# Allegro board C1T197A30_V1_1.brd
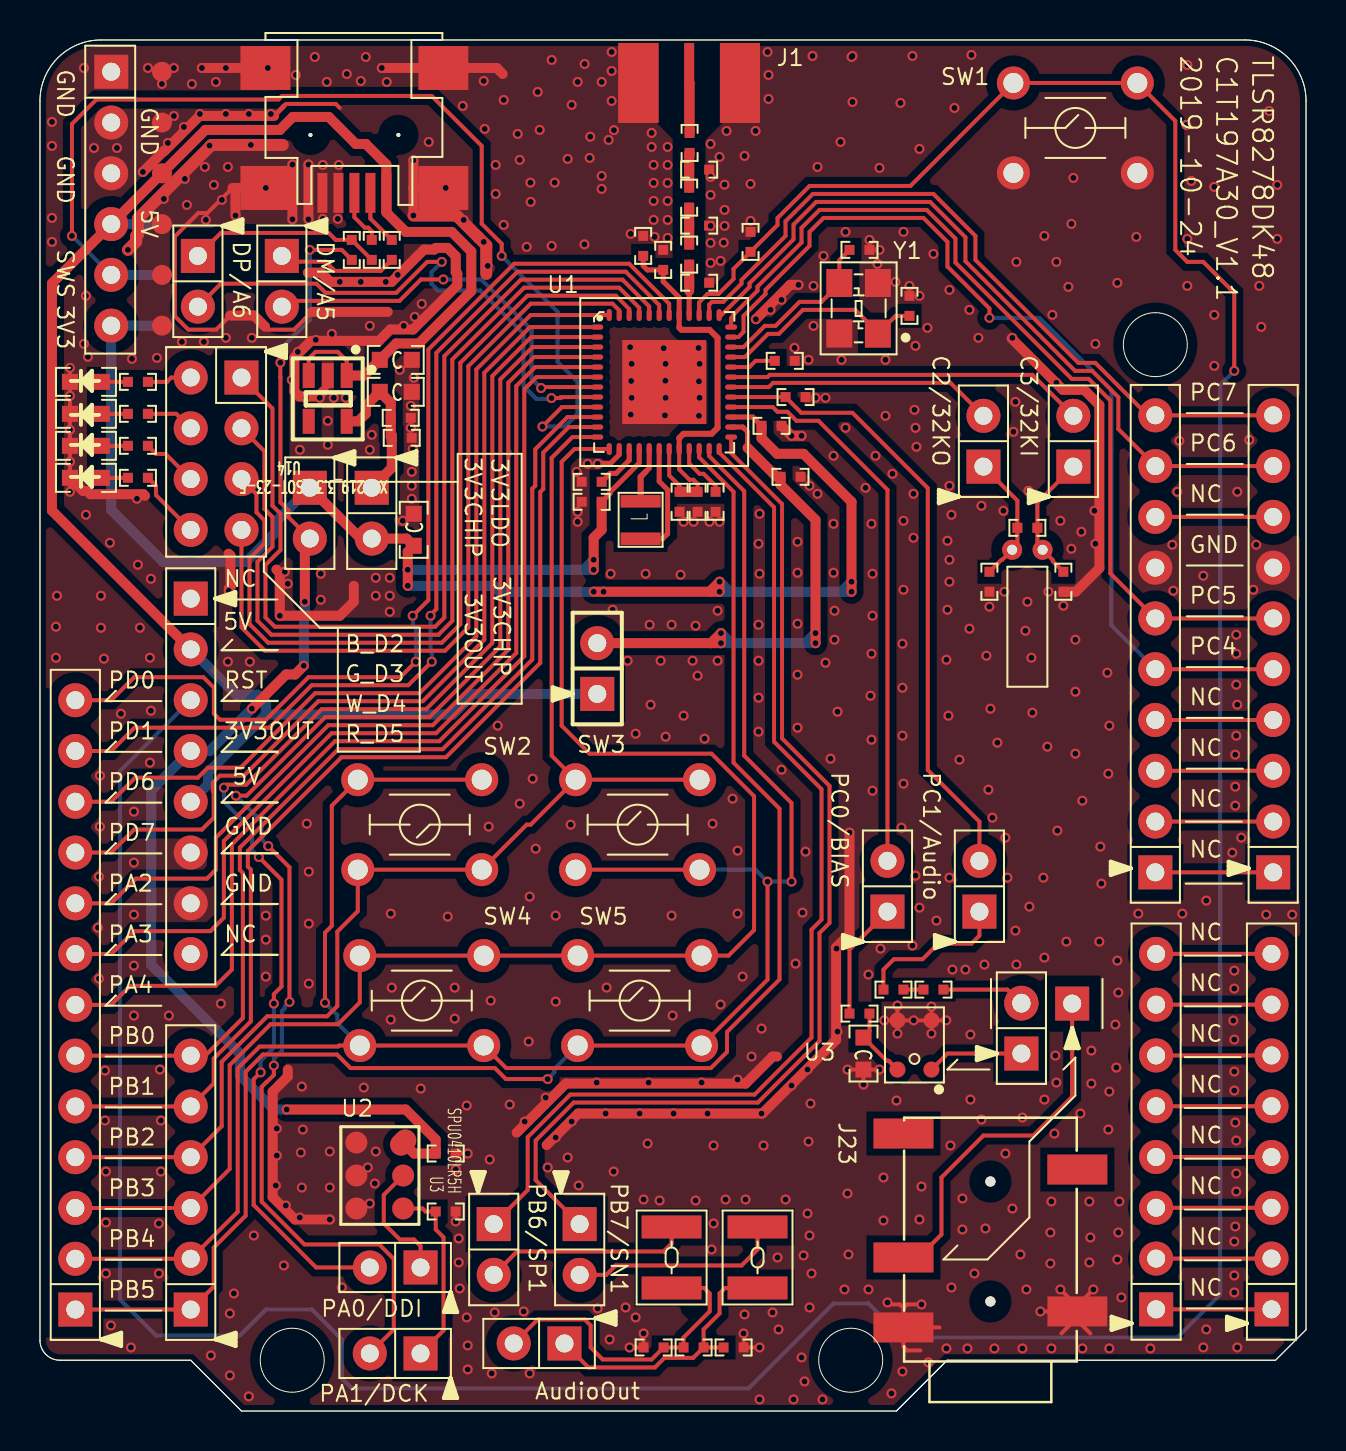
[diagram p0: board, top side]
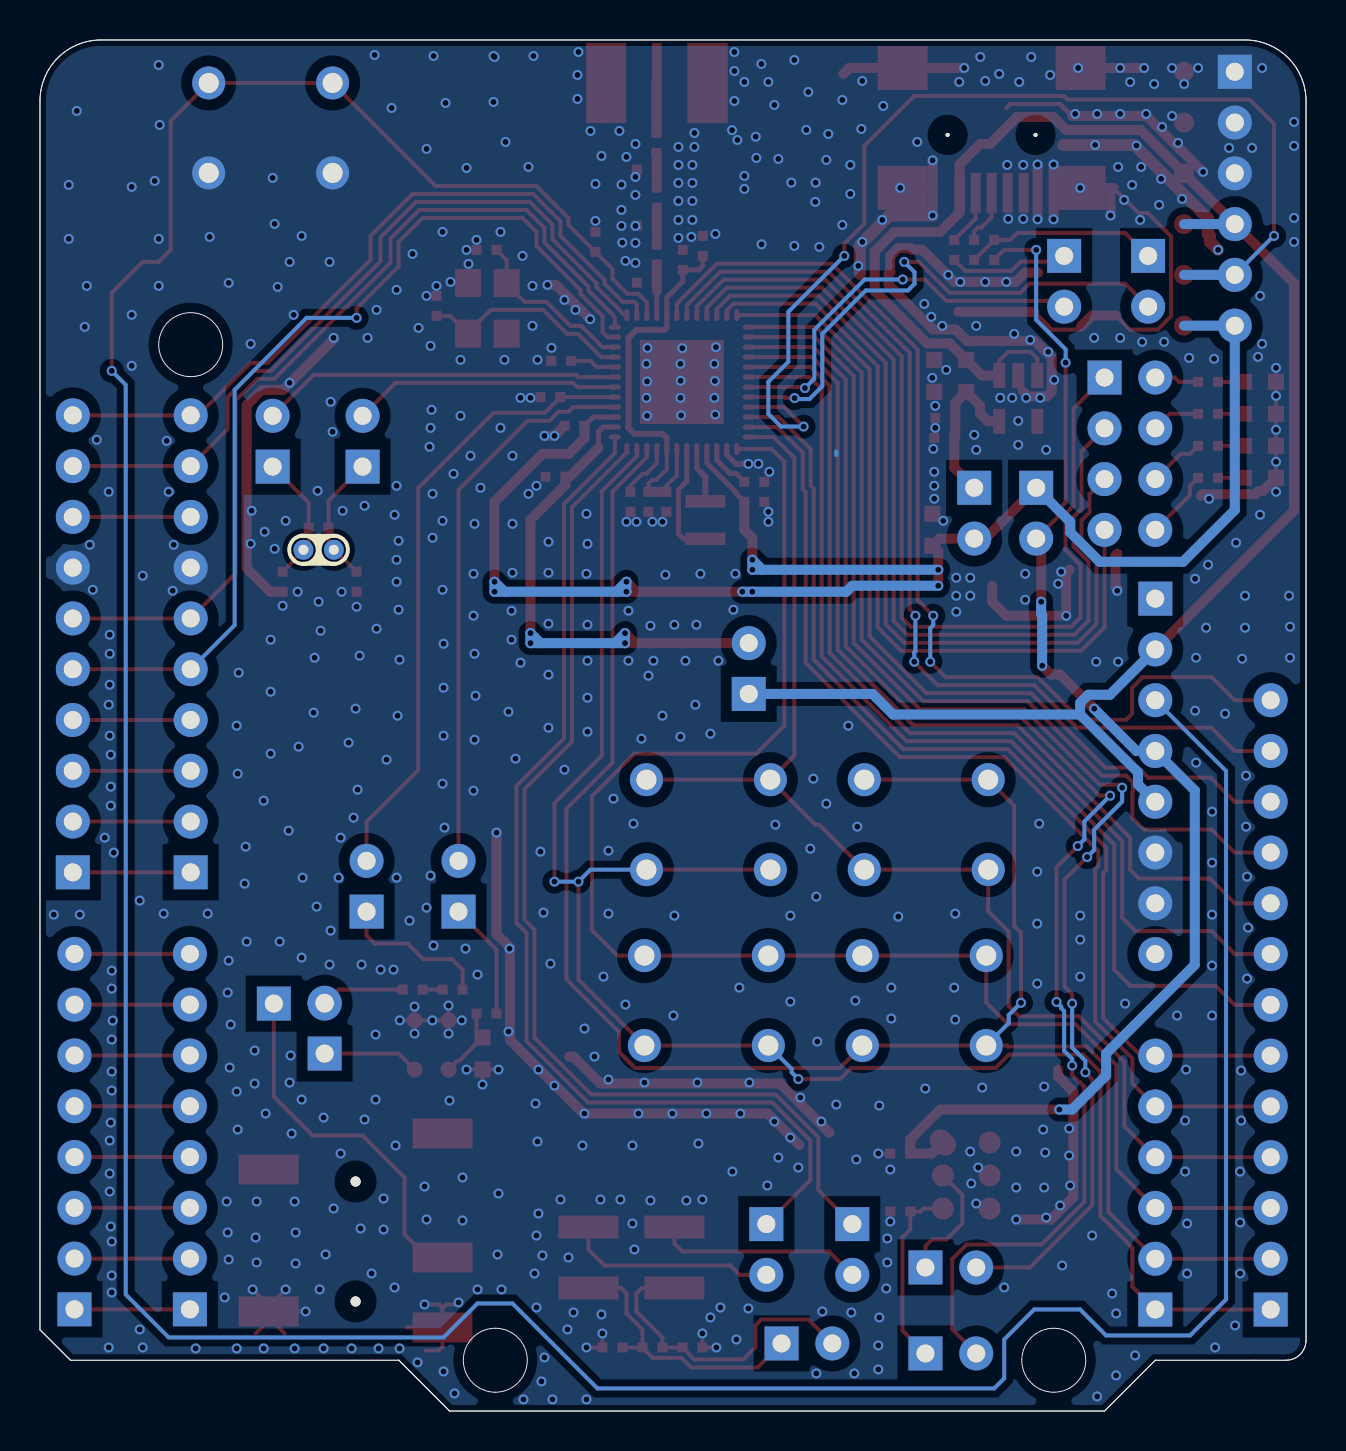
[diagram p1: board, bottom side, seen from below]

Outline 63.34 x 68.58 mm; copper layers: TOP, BOTTOM. Coordinates in mm from the lower left corner of the outline.
Outline path: 0,65.53 arc(0.89,67.69) 3.05,68.58 ; 0,65.53 0,3.54 ; 0,65.53 arc(0.89,67.69) 3.05,68.58 ; 0,65.53 0,3.54 ; 3.05,68.58 60.29,68.58 ; 3.05,68.58 60.29,68.58 ; 0,3.54 arc(0.29,2.83) 1,2.54 ; 0,3.54 arc(0.29,2.83) 1,2.54 ; 1,2.54 7.54,2.54 ; 1,2.54 7.54,2.54 ; 7.54,2.54 10.08,0 ; 7.54,2.54 10.08,0 ; 60.29,68.58 arc(62.45,67.69) 63.34,65.53 ; 60.29,68.58 arc(62.45,67.69) 63.34,65.53 ; 10.08,0 42.85,0 ; 10.08,0 42.85,0 ; 42.85,0 45.39,2.54 ; 42.85,0 45.39,2.54 ; 42.85,0 45.39,2.54 ; 45.39,2.54 61.82,2.54 ; 45.39,2.54 61.82,2.54 ; 63.34,65.53 63.34,4.06 ; 63.34,65.53 63.34,4.06 ; 61.82,2.54 63.34,4.06 ; 61.82,2.54 63.34,4.06 ; 12.62,4.14 arc(14.22,2.54) 12.62,0.94 arc(11.02,2.54) 12.62,4.14 ; 40.56,4.14 arc(42.16,2.54) 40.56,0.94 arc(38.96,2.54) 40.56,4.14 ; 55.8,54.94 arc(57.4,53.34) 55.8,51.74 arc(54.2,53.34) 55.8,54.94

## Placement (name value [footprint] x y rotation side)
C1  0.1uF  [0402]  31.18 57.58 270 top
C2  2.2uF  [0402]  30.18 58.28 270 top
C3  NC  [0402]  41 58.08 180 top
C4  NC  [0402]  43.5 55.28 270 top
C6  1.5pF  [0402]  32.98 59.29 180 top
C7  2pF  [0402]  32.98 62.09 180 top
C8  220pF  [0402]  32.48 57.84 90 top
C9  NC  [0402]  32.98 56.44 180 top
C10  NC  [0402]  47.5 41.48 90 top
C11  NC  [0402]  51.2 41.48 90 top
C13  1uF  [0402]  36.6 49.28 0 top
C14  1uF  [0402]  27.6 46.48 0 top
C15  1uF  [0402]  35.55 58.48 270 top
C16  1uF  [0402]  27.6 45.48 180 top
C17  0.1uF  [0402]  32.9 45.48 270 top
C18  1uF  [0402]  32 45.48 270 top
C19  1uF  [0402]  33.8 45.48 270 top
C20  NC  [0402]  30.7 3.18 0 top
C21  220nF  [0402]  32.7 3.18 0 top
C22  0.1uF  [0402]  20.3 12.88 0 top
C23  NC  [0402]  34.7 3.18 0 top
C24  10nF  [0402]  44.7 21.08 0 top
C25  10pF  [0402]  37.8 50.72 180 top
C26  4.7uF  [0603C]  41.2 17.88 270 top
C27  1uF  [0402]  37.55 46.73 0 top
C29  10uF  [0603C]  18.7 44.08 90 top
C30  10uF  [0603C]  17.8 52.58 0 top
C31  10uF  [0603C]  17.8 50.98 0 top
C32  1nF  [0402]  18.1 48.68 0 top
C33  0.1uF  [0402]  18.05 49.68 0 top
C34  1uF  [0402]  37.26 52.53 0 top
D1  Blue  [0603-LED]  2.3 51.48 180 top
D2  Green  [0603-LED]  2.3 49.88 180 top
D3  White  [0603-LED]  2.3 48.28 180 top
D4  Red  [0603-LED]  2.3 46.68 180 top
J1  RFIN  [SMA-H]  32.48 66.43 270 top
J2  32KPC3  [HDR254F-1X2X850]  51.7 49.78 270 top
J4  32KPC2  [HDR254F-1X2X850]  47.2 49.78 270 top
J6  HEADER 13  [HDR254F-1X13X850]  1.77 35.56 270 top
J7  Left_Ardunio  [HDR254F-1X8X850]  7.54 22.86 90 top
J8  Right_Ardunio  [HDR254F-1X10X850]  55.8 49.81 270 top
J9  Right_Telink  [HDR254F-1X10X850]  61.7 49.81 270 top
J11  Right_Ardunio  [HDR254F-1X8X850]  55.84 22.87 270 top
J12  Right_Telink  [HDR254F-1X8X850]  61.61 22.87 270 top
J13  Left_Ardunio  [HDR254F-1X6X850]  7.54 17.78 270 top
J16  SDMB4  [HDR254F-1X2X850]  22.7 6.81 90 top
J17  SDMB5  [HDR254F-1X2X850]  27 6.81 90 top
J18  Debug  [HDR254F-1X6X850_TELINKDEBUG]  3.56 54.29 90 top
J20  MICPC0  [HDR254F-1X2X850]  42.4 27.52 270 top
J22  MICPC1  [HDR254F-1X2X850]  47 27.52 270 top
J23  PJ327  [PJ-327]  47.55 2.48 180 top
J26  USB_MiniABF  [USB-MINI-F5]  15.73 60.93 180 top
J27  DM/A5  [HDR254F-1X2X850]  12.1 55.24 90 top
J28  DP/A6  [HDR254F-1X2X850]  7.9 55.24 90 top
J29  Chip3V3  [HDR254F-1X2X850]  16.6 43.64 90 top
J35  IO3V3  [HDR254F-1X2X850]  13.5 43.64 90 top
J36  MICIN  [HDR254F-1X2X850]  49.1 20.42 270 top
J37  LINEIN  [HDR254F-1X2X850]  49.1 20.38 0 top
J38  LED  [HDR254F-2X4X850]  10.08 41.54 90 top
J39  AudioOut  [HDR254F-1X2X850]  23.7 3.38 0 top
J40  DMICCK  [HDR254F-1X2X850]  16.5 2.88 0 top
J41  DMICDI  [HDR254F-1X2X850]  16.5 7.18 0 top
J42  RF_SOC_5V  [HDR254F-1X2X850]  27.88 38.41 270 top
L2  2.4nH  [0402]  32.48 60.69 90 top
L3  4.7uH  [2X2_5MM]  36.8 33.28 90 top
L4  150uH  [INDM3025X25]  31.6 7.68 270 top
L5  150uH  [INDM3025X25]  35.9 7.68 270 top
L6  1.5nH  [0402]  32.5 63.43 90 top
R1  NC  [0402]  49.4 44.18 0 top
R2  100K  [0402]  20.3 9.98 180 top
R3  1K  [0402]  4.9 51.48 180 top
R4  1K  [0402]  4.9 49.88 180 top
R5  1K  [0402]  4.9 48.28 180 top
R6  1K  [0402]  4.9 46.68 180 top
R7  0R  [0402]  41 19.88 0 top
R8  000R  [0402]  42.7 21.08 0 top
R10  33  [0402R]  17.6 58.08 270 top
R11  33  [0402R]  16.6 58.08 270 top
R12  NC/1.5K  [0402R]  15.6 58.08 270 top
SW1  SW4PIN_4.5x4.5  [BUTDIP4P_5P0X3P0]  51.8 64.18 0 top
SW2  Key1  [BUTDIP4P_5P0X3P0]  19 29.33 180 top
SW3  Key2  [BUTDIP4P_5P0X3P0]  29.9 29.33 0 top
SW4  Key3  [BUTDIP4P_5P0X3P0]  19.1 20.53 0 top
SW5  Key4  [BUTDIP4P_5P0X3P0]  30 20.53 0 top
U1  TLSR8278F1KET48  [QFN_7X7_48PIN_0P5_4P20X4P20]  31.23 51.47 0 top
U2  SPM0423HM4H-WB  [DMIC_SPM0423HM4H-WB]  17 11.78 270 top
U3  MWW7037AT2  [GA_BFA423_A83]  43.75 18.31 180 top
U4  CE1132-33M  [SOT-23-5]  14.4 50.65 180 top
Y1  24MHz-12pF-+/-20ppm  [OSCCC250X320X110]  40.96 55.16 180 top
Y2  32.768KHz - 9pf - +/-20ppm  [OSC_2X6]  49.4 39.08 90 top

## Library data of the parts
C1 C2 C13 C16-C19 C22 C27 C29-C34 = C1005X5R1C104K
C3 C4 C20 C23 = C1005_NC
C6-C11 = C1608_NC
C14 C15 C24 = C1005X5R1C105K
C21 = C1005X5R1C224M
C25 = C1005C0G1H223J
C26 = C1608X5R0J475M
D1-D4 = 0603D_Green
J1 = SMA_JACK_2
J2 J4 J16 J17 J20 J22 J27-J29 J35-J37 J39-J42 = B2S_3: User Part Number: pn; Tolerance: RichardLC
J6 = HEADER 13: User Part Number: pn; Tolerance: RichardLC
J7 J11 J12 = HEADER 8: User Part Number: pn; Tolerance: RichardLC
J8 J9 = HEADER 10: Tolerance: RichardLC; User Part Number: pn
J13 = HEADER 6: User Part Number: pn; Tolerance: RichardLC
J18 = CON_0.54mm_2x6: User Part Number: pn; Tolerance: RichardLC
J23 = PJ327_2
J26 = USB_MiniABF_5pin: Tolerance: RichardLC; User Part Number: pn
J38 = HEADER 4X2: User Part Number: pn; Tolerance: RichardLC
L2 L6 = MLK1608_000R
L3 = IND_0
L4 L5 = IND_150uH_3025
R1 = RS0603K102JT
R2 = RS0402K104JT
R3-R6 = RS0402K102JT
R7 R8 = RS0402K472JT
R10 R11 = RS0603K330JT
R12 = RS0603K152JT
SW1-SW5 = SW4PIN_0.5
U1 = TLSR8278F1KET48_2
U2 = LD1117/SO_0
U3 = MULPS4CX-RM5_0
U4 = XC6219_6.3V_SOT-23-5
Y1 = CRYSTAL4/SM_0: Tolerance: RichardLC
Y2 = OSC_2x6_2pin_16Mhz

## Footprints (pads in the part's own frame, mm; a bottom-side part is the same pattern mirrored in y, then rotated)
2X2_5MM
  rect 0.625x2 smd: 1(10.35,6.75) 2(12.225,6.75)
0402
  rect 0.5x0.5 smd: 1(-0.5,0) 2(0.5,0)
0402R
  rect 0.5x0.5 smd: 1(-0.5,0) 2(0.5,0)
0603-LED
  rect 0.8x0.8 smd: A(-0.8,0) C(0.8,0)
0603C
  rect 0.8x0.8 smd: 1(-0.8,0) 2(0.8,0)
BUTDIP4P_5P0X3P0
  round 1.65 hole 1: 1(-3.1,2.25) 2(-3.1,-2.25) 3(3.1,2.25) 4(3.1,-2.25)
DMIC_SPM0423HM4H-WB
  round 1.1 smd: 1(-1.65,-1.17) 2(0,-1.17) 3(1.65,-1.17) 4(1.65,1.17) 5(0,1.17)
  oval 1.4x1.1 smd rot 135: 6(-1.65,1.17)
GA_BFA423_A83
  round 0.8 smd: 1(-0.85,1.23) 2(-0.85,-1.23) 3(0.85,-1.23) 4(0.85,1.23)
HDR254F-1X2X850
  rect 1.7x1.7 hole 0.9: 1(2.54,0)
  round 1.7 hole 0.9: 2(0,0)
HDR254F-1X6X850
  rect 1.7x1.7 hole 0.9: 1(12.7,0)
  round 1.7 hole 0.9: 2(10.16,0) 3(7.62,0) 4(5.08,0) 5(2.54,0) 6(0,0)
HDR254F-1X6X850_TELINKDEBUG
  rect 1.7x1.7 hole 0.9: 1(12.7,0)
  round 1.7 hole 0.9: 2(10.16,0) 3(7.62,0) 4(5.08,0) 5(2.54,0) 6(0,0)
  round 1 smd: 7(0,-2.54) 8(2.54,-2.54) 9(5.08,-2.54) 10(7.62,-2.54) 11(10.16,-2.54) 12(12.7,-2.54)
HDR254F-1X8X850
  rect 1.7x1.7 hole 0.9: 1(17.78,0)
  round 1.7 hole 0.9: 2(15.24,0) 3(12.7,0) 4(10.16,0) 5(7.62,0) 6(5.08,0) 7(2.54,0) 8(0,0)
HDR254F-1X10X850
  rect 1.7x1.7 hole 0.9: 1(22.86,0)
  round 1.7 hole 0.9: 2(20.32,0) 3(17.78,0) 4(15.24,0) 5(12.7,0) 6(10.16,0) 7(7.62,0) 8(5.08,0) 9(2.54,0) 10(0,0)
HDR254F-1X13X850
  rect 1.7x1.7 hole 0.9: 1(30.48,0)
  round 1.7 hole 0.9: 2(27.94,0) 3(25.4,0) 4(22.86,0) 5(20.32,0) 6(17.78,0) 7(15.24,0) 8(12.7,0) 9(10.16,0) 10(7.62,0) 11(5.08,0) 12(2.54,0) 13(0,0)
HDR254F-2X4X850
  rect 1.7x1.7 hole 0.9: 1(10.16,0)
  round 1.7 hole 0.9: 2(10.16,2.54) 3(7.62,0) 4(7.62,2.54) 5(5.08,0) 6(5.08,2.54) 7(2.54,0) 8(2.54,2.54)
INDM3025X25
  rect 1.15x3 smd: 1(-1.525,0) 2(1.525,0)
OSC_2X6
  round 1 hole 0.5: 1(4,0.76) 2(4,-0.76)
OSCCC250X320X110
  rect 1.3x1.4 smd: 1(-0.965,1.265) 2(-0.965,-1.265) 3(0.965,-1.265) 4(0.965,1.265)
PJ-327
  round 0.5 hole 1: (0,-3) (0,-9)
  rect 3x1.5 smd: 1(-4.35,-2.5) 2(4.35,-5.2) 3(-4.35,-9.6) 4(4.35,-11.4) 5(4.35,-1.7)
QFN_7X7_48PIN_0P5_4P20X4P20
  oval 0.6x0.26 smd: 1(-3.35,2.75) 2(-3.35,2.25) 3(-3.35,1.75) 4(-3.35,1.25) 5(-3.35,0.75) 6(-3.35,0.25) 7(-3.35,-0.25) 8(-3.35,-0.75) 9(-3.35,-1.25) 10(-3.35,-1.75) 11(-3.35,-2.25) 12(-3.35,-2.75) 25(3.35,-2.75) 26(3.35,-2.25) 27(3.35,-1.75) 28(3.35,-1.25) 29(3.35,-0.75) 30(3.35,-0.25) 31(3.35,0.25) 32(3.35,0.75) 33(3.35,1.25) 34(3.35,1.75) 35(3.35,2.25) 36(3.35,2.75)
  oval 0.26x0.6 smd: 13(-2.75,-3.35) 14(-2.25,-3.35) 15(-1.75,-3.35) 16(-1.25,-3.35) 17(-0.75,-3.35) 18(-0.25,-3.35) 19(0.25,-3.35) 20(0.75,-3.35) 21(1.25,-3.35) 22(1.75,-3.35) 23(2.25,-3.35) 24(2.75,-3.35) 37(2.75,3.35) 38(2.25,3.35) 39(1.75,3.35) 40(1.25,3.35) 41(0.75,3.35) 42(0.25,3.35) 43(-0.25,3.35) 44(-0.75,3.35) 45(-1.25,3.35) 46(-1.75,3.35) 47(-2.25,3.35) 48(-2.75,3.35)
  rect 4.2x4.2 smd: 49(0,0)
SMA-H
  rect 4x0.5 smd: 1(0,0)
  rect 4x2 smd: 2(0,-2.54) 3(0,2.54) 4(0,-2.54) 5(0,2.54)
SOT-23-5
  rect 0.6x1.25 smd: 1(-0.95,-1.145) 2(0,-1.145) 3(0.95,-1.145) 4(0.95,1.145) 5(-0.95,1.145)
USB-MINI-F5
  round 0.2 hole 0.9 unplated: (-2.2,-2.9) (2.2,-2.9)
  rect 0.5x2 smd: 1(-1.6,0) 2(-0.8,0) 3(0,0) 4(0.8,0) 5(1.6,0)
  rect 2.5x2.2 smd: 6(-4.45,-6.25) 7(4.45,-6.25) 8(-4.45,-0.25) 9(4.45,-0.25)

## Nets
1V4: C1.2 C2.2 C17.1 C18.1 U1.19(VDD1V2) U1.20(AVDD1V2#20) U1.41(AVDD1V2#41)
3V3: C31.1 C32.1 C33.1 J29.1 U4.5(VOUT)
GND: C1.1 C2.1 C3.1 C4.1 C6.1 C7.1 C9.1 C10.1 C11.1 C13.2 C14.1 C15.1 C16.2 C17.2 C18.2 C19.2 C20.1 C22.2 C23.2 C25.1 C26.2 C27.2 C29.2 C30.2 C31.2 C32.2 C33.2 C34.2 D1.C(CATHODE) D2.C(CATHODE) D3.C(CATHODE) D4.C(CATHODE) J1.2 J1.3 J1.4 J1.5 J7.6 J7.7 J8.7 J9.7 J18.1 J18.2 J18.3 J18.10 J18.11 J18.12 J23.1 J23.5 J26.4(ID) J26.5(GND) J26.6(S1) J26.7(S2) J26.8(S3) J26.9(S4) R2.1 SW1.2 SW1.4 U1.14(DVSS) U1.49(GND) U2.1(GND#1) U2.2(SE) U2.3(GND#3) U3.2(GND#2) U3.3(GND#3) U4.2(VSS) Y1.2 Y1.4
TL_32KI_C3: J2.2 U1.31(P1/URX/SCK/32KIN/C[3])
TL_32KO_C2: J4.2 U1.30(P0/7816TRX/UTX/SDA/32KO/C[2])
TL_ANT: C8.1 C9.2 U1.40(ANT)
TL_AS0_C5: J8.6 J9.6 U1.36(P3N/URX/ATSEL0/C[5])
TL_AS1_C6: J8.9 J9.9 U1.37(CYC2LNA/ATSEL1/P4N/C[6])
TL_AS2_C7: J8.10 J9.10 U1.38(CYC2PA/ATSEL2/P5N/C[7])
TL_AUDIO_C1: C25.2 J22.2 U1.29(SCK/P1N/P0/AUDIO_IN/C[1])
TL_C0: J20.2 U1.28(SDA/P4N/URTS/MDEC/C[0])
TL_CK_A4: J6.7 U1.6(CK/SCL/URTS/P2/A[4])
TL_CN_D6: J6.11 U1.48(CN/URX/ATSEL0/D[6])
TL_D0: J6.13 U1.42(CYC2LNA/CMP_D/7816TRX/UTX/MDEC/)
TL_D1: J6.12 U1.43(CYC2PA/CMP_DF/UCTS/D[1])
TL_D7: J6.10 U1.1(CK/SCL/I2SBCK/7816TRX/UTX/D[7])
TL_DI_A3: J6.8 U1.5(DI/SDA/UCTS/P1/A[3])
TL_DM_A5: J27.2 U1.7(DM/A[5])
TL_DMICCK_A1: J40.2 U1.3(DMIC_CLK/7816CLK/I2SCLK/A[1])
TL_DMICDI_A0: J41.2 U1.2(DMIC_DI/P0N/URX/MDEC/A[0])
TL_DO_A2: J6.9 U1.4(DO/UTX/P0/A[2])
TL_DP_A6: J28.2 U1.8(DP(SWS)/A[6])
TL_IO: C22.1 J7.4 J35.2 R12.2 U2.6(POWER)
TL_KEY_B2: J6.4 J13.4 SW2.1 SW2.3 SW3.1 SW3.3 U1.12(P5/UCTS/CYC2LNA/B[2])
TL_KEY_B3: J6.3 J13.3 SW4.1 SW4.3 SW5.1 SW5.3 U1.13(P0N/URTS/CYC2PA/B[3])
TL_KEY_B4: J6.2 J13.2 SW2.2 SW2.4 SW4.2 SW4.4 U1.22(SDMP0/P4/CMP_D/B[4])
TL_KEY_B5: J6.1 J13.1 SW3.2 SW3.4 SW5.2 SW5.4 U1.23(SDMN0/P5/CMP_DF/B[5])
TL_P0_D5: J38.7 U1.47(P0/CMP_D/P0N/D[5])
TL_P1N_D3: J38.3 U1.45(P1N/I2SSDI/7816TRX/UTX/D[3])
TL_P2_C4: J8.5 J9.5 U1.35(P2/UCTS/P0/C[4])
TL_P2N_D4: J38.5 U1.46(SWM/I2SSDO/P2N/D[4])
TL_P3_D2: J38.1 U1.44(CN/I2SLR/P3/D[2])
TL_RST: C15.2 J7.3 SW1.1 SW1.3 U1.39(RESETB)
TL_SDMN1_B7: J17.1 U1.25(SDMN1/DO/URX/B[7])
TL_SDMP1_B6: J16.1 U1.24(SDMP1/DI/SDA/URTS/B[6])
TL_SWS_A7: J18.5 J18.8 U1.9(SWS/URTS/A[7])
TL_URX_B0: J6.6 J13.6 U1.10(P3/URX/ATSEL1/MDEC/B[0])
TL_UTX_B1: J6.5 J13.5 U1.11(P4/UTX/ATSEL2/B[1])
TL_VBUS: C27.1 J42.2 U1.26(VBUS)
TL_VDD: C13.1 C16.1 C29.1 J18.6 J18.7 J29.2 J35.1 U1.16(VDD_IO) U1.27(VDD3)
TL_XC1: C3.2 U1.34(XC1) Y1.3
TL_XC2: C4.2 U1.33(XC2) Y1.1
USB_5V: C30.1 J7.2 J7.5 J18.4 J18.9 J26.1(V_BUS) J42.1 U4.1(VIN) U4.3(CE)
N19472288: J38.4 R4.1
N19472291: J38.8 R6.1
N19472372: J16.2 L4.1
N19472375: J17.2 L5.1
N19472414: C20.2 C21.1 J39.2 L4.2
N19472431: C21.2 C23.1 J39.1 L5.2
N19472505: J38.2 R3.1
N19497696: J38.6 R5.1
N19519268: C11.2 J2.1 R1.2 Y2.2
N19519271: C10.2 J4.1 R1.1 Y2.1
N19526123: J28.1 R11.2 R12.1
N19526133: J26.3(D+) R11.1
N19526168: J26.2(D-) R10.1
N19527038: J27.1 R10.2
N19581488: J20.1 R7.1
N19581502: C26.1 R7.2 U3.4(VDD)
N19581635: C24.1 R8.2
N19581732: J23.2 J37.1
N19602515: C24.2 J36.2 J37.2
N19603583: J22.1 R8.1
N19606656: J40.1 R2.2 U2.4(CLOCK)
N19606659: J41.1 U2.5(DATA)
N19611817: J8.4 J9.4
N19611824: J8.3 J9.3
N19611831: J8.2 J9.2
N19611838: J8.1 J9.1
N19611845: J8.8 J9.8
N19611852: J11.8 J12.8
N19611859: J11.6 J12.6
N19611866: J11.7 J12.7
N19611873: J11.5 J12.5
N19611880: J11.4 J12.4
N19611887: J11.3 J12.3
N19611894: J11.2 J12.2
N19611901: J11.1 J12.1
N19648539: C34.1 U1.32(VMID)
N19648573: C14.2 U1.15(VDD1V)
N19648583: L3.1 U1.18(VDCDC)
N19648603: L3.2 U1.17(VDCDC_SW)
N19648651: C19.1 U1.21(VDD_F)
N19650305: C6.2 C8.2 L2.1
N19650315: C7.2 L2.2 L6.1
N19656188: J1.1 L6.2
N194723011: D4.A(ANODE) R6.2
N194723090: D1.A(ANODE) R3.2
N194723171: D2.A(ANODE) R4.2
N194723250: D3.A(ANODE) R5.2
N195815302: J36.1 U3.1(OUTPUT)

Pads without a net: J7 1 8; J23 3 4; U4 4

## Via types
v1: diameter 0.5, hole 0.3, TOP to BOTTOM, 735 vias

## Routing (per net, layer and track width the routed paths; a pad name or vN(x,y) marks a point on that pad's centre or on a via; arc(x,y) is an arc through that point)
1V4: length 20
  TOP w0.2: C17.1 32.9,46.38 32.7,46.58 32.5,46.58 31.98,47.1 U1.20 ; C18.1 32,46.28 31.48,46.8 U1.19
  TOP w0.25: U1.20 31.98,48.66 ; 31.98,54.2 U1.41 31.98,55.7 31.18,56.5 C1.2 30.38,57.08 30.18,57.28 C2.2
  TOP w0.3: 31.98,54.2 32.1,54.08 33.5,54.08 33.9,53.68 33.9,49.18 33.6,48.88 32.19,48.88 31.98,48.66
  TOP w0.5: C18.1 C17.1
3V3: length 8
  TOP w0.5: U4.5 15.93,49.51 16.3,49.88 16.3,50.28 C31.1 17.55,50.43 C33.1 17.55,48.73 C32.1 17.6,47.18 J29.1
GND: length 212.7
  TOP w0.2: J23.5 45,4.18 ; J23.5 43.2,3.21 43.38,3.03 44.05,3.03 ; J23.5 43.2,5.15 ; C26.2 v1(40.4,17.08) ; C26.2 v1(41.2,16.33) ; C26.2 v1(42,17.08) ; 52.55,3.88 51.9,4.53 51.9,4.68 ; J23.1 51.9,4.68 ; J23.1 51.9,5.23 ; J23.1 v1(50.05,4.98) ; 51.9,4.68 51.1,3.88 ; U4.2 14.4,51.23 14.17,51 ; 9.63,61.18 8.38,59.92 7.92,59.92 6.75,58.75 6.75,54.76 7.42,54.09 8.81,54.09 9.52,54.8 ; v1(1.5,52.18) D1.C v1(1.5,50.78) D2.C v1(1.5,49.08) D3.C v1(1.5,47.48) D4.C v1(1.5,45.98) ; U3.2 v1(45.34,19.54) ; U3.2 v1(44.6,18.88) ; U3.2 v1(44.6,20.23) ; U3.2 v1(43.71,19.54) U3.3 ; v1(30.2,3.88) C20.1 v1(29.5,3.18) ; 51.9,5.23 51.9,5.28 v1(52.7,6.08) ; 51.9,5.23 v1(51.05,6.08) ; U3.3 v1(42.9,20.28) ; U3.3 v1(42.9,18.88) ; U3.3 v1(42.24,19.54) ; 43.2,5.15 43.02,5.33 42.3,5.33 ; 43.2,5.15 43.38,5.33 v1(44.1,5.33) ; 15,65.18 14.8,65.38 12.31,65.38 12.21,65.27 ; 13.6,54.98 12.71,54.09 11.41,54.09 11.26,54.24 ; v1(36,3.18) C23.2 v1(35.2,3.88) ; R2.1 v1(20.8,9.48) ; C22.2 v1(21.4,12.88)
  TOP w0.25: 12.21,65.27 11.71,64.78 ; U1.14 28.98,47.84 28.52,47.38
  TOP w0.3: v1(27.9,47.38) 28.52,47.38
  TOP w0.5: 11.71,64.78 7.98,64.78 6.24,63.04 6.21,63.04 v1(5.15,61.98) ; v1(12.63,62.35) v1(12.63,59.61) ; 9.52,54.8 10.7,54.8 11.26,54.24 ; v1(11.4,67.18) J26.7 v1(8.1,67.18) ; 18.68,61.18 v1(18.68,59.8) ; 18.68,61.18 v1(18.68,62.56) ; 18.68,61.18 J26.8 v1(20.3,61.18) ; D4.C 2.16,46.02 2.37,46.02 2.53,45.86 5.18,45.86 5.26,45.78 ; 36.87,17.73 36.65,17.73 35.3,16.38 26.31,16.38 23.85,13.92 ; v1(37.95,56.33) 37.53,56.33 v1(35.82,54.61) ; 15.7,41.28 15.7,40.48 15,39.78 v1(12,39.78) 12,41.92 11.83,42.09 ; v1(13.43,62.35) v1(13.43,59.61) ; 13.4,56.94 14.06,56.94 14.52,56.48 v1(15,56.48) v1(16.05,56.48) v1(17.3,56.48) 17.59,56.48 19.21,58.1 19.73,58.1 19.81,58.18 20.39,58.18 20.8,57.77 20.8,56.97 20.88,56.89 20.88,56.31 18.67,54.1 17.53,54.1 16.96,53.53 13.56,53.53 12.73,52.7 12.73,51 12.97,50.75 13.92,50.75 14.17,51 ; v1(40.5,28.93) 40.5,23.86 39.83,23.19 39.83,18.57 36.14,14.88 v1(36.1,14.88) v1(33.4,14.88) v1(31.7,14.88) v1(30,14.88) v1(28.3,14.88) 26.93,14.88 25.35,13.3 ; v1(11.3,61.18) J26.9 9.78,61.18 ; 12.4,17.08 12.4,16.73 11.64,15.97 11.64,10.7 12.76,9.58 v1(14.5,9.58) ; 9.78,61.18 v1(9.78,59.8) ; 9.78,61.18 9.63,61.18 ; 23.15,66.88 22.85,67.18 J26.6 v1(17.1,67.18) ; v1(38.1,48.78) v1(37.6,48.78) C13.2 ; 13.6,54.98 17.4,54.98 ; 48.61,53.65 51.18,51.08 52.24,51.08 53,50.32 53,42.16 51.82,40.98 C11.1 ; v1(9.45,41.03) 9.45,41.13 9.53,41.21 9.53,42.79 9.43,42.88
  TOP w0.6: 12.15,63.33 v1(10.55,63.33) 8.58,63.33 4.91,59.66 4.91,58.87 4.81,58.77 4.81,58.49 v1(4.4,58.08) ; 22.33,56.88 22.33,58.31 21.93,58.71 20.84,59.8 v1(18.68,59.8)
  BOTTOM w0.2: 23.5,48 23.5,47.82
  vias: v1(0.6,64.48) v1(0.6,63.28) v1(0.6,59.68) v1(0.6,58.48) v1(0.85,40.78) v1(0.8,39.23) v1(0.8,37.68) v1(2.2,67.18) v1(2.2,53.38) v1(2.3,55.78) v1(2.3,44.83) v1(2.4,52.73) v1(2.7,63.18) v1(2.9,24.18) v1(3.05,40.78) v1(3.05,39.18) v1(3,31.78) v1(3,29.23) v1(2.95,26.73) v1(2.95,21.63) v1(3.2,37.63) v1(3.25,17.03) v1(3.25,14.53) v1(3.3,11.98) v1(3.3,9.43) v1(3.3,6.88) v1(3.5,43.43) v1(3.55,4.28) v1(3.85,63.18) v1(4.05,34.88) v1(4.55,3.18) v1(4.6,52.63) v1(4.7,29.98) v1(4.7,27.43) v1(4.7,24.83) v1(4.7,22.28) v1(4.7,19.78) v1(4.85,45.63) v1(4.9,42.33) v1(5,39.18) v1(5.4,67.18) v1(5.55,41.63) v1(5.5,37.68) v1(5.55,35.03) v1(5.5,32.43) v1(5.85,52.68) v1(6,17.08) v1(6.05,14.53) v1(6.05,11.98) v1(5.95,9.38) v1(5.95,6.88) v1(6.1,66.38) v1(6.2,60.63) v1(6.4,63.43) v1(6.45,19.78) v1(6.7,67.18) v1(6.7,64.78) v1(7.1,53.48) v1(7.2,64.23) v1(7.25,61.63) v1(7.35,60.33) v1(7.6,66.38) v1(8,64.88) v1(8.25,62.23) v1(8.2,53.48) v1(8.3,59.58) v1(8.48,63.3) v1(8.55,2.78) v1(8.7,61.33) v1(8.8,66.48) v1(9.1,60.58) v1(9.05,20.38) v1(9.3,67.18) v1(9.3,64.88) v1(9.3,53.68) v1(9.4,62.23) v1(9.4,37.48) v1(9.5,4.88) v1(9.5,1.78) v1(9.7,5.88) v1(10.45,64.88) v1(10.45,0.73) v1(10.5,37.48) v1(10.6,53.68) v1(10.7,8.78) v1(11.3,24.78) v1(11.3,23.58) v1(11.3,21.73) v1(11.55,64.88) v1(11.85,14.13) v1(11.85,12.78) v1(11.8,11.28) v1(12.25,41.98) v1(12.2,7.28) v1(12.3,10.28) v1(12.4,41.38) v1(12.6,51.58) v1(12.8,66.83) v1(12.9,52.98) v1(13,48.08) v1(13,9.68) v1(13.1,16.23) v1(13.05,12.93) v1(13.1,11.18) v1(13.15,14.08) v1(13.3,50.68) v1(13.35,29.38) v1(13.45,26.98) v1(13.45,24.38) v1(13.45,21.38) v1(13.75,67.73) v1(13.8,53.58) v1(14,50.68) v1(14.05,41.88) v1(14.05,40.58) v1(14.15,62.33) v1(14.15,59.63) v1(14.35,66.48) v1(14.4,49.53) v1(14.4,48.33) v1(14.5,12.98) v1(14.5,11.18) v1(14.6,53.88) v1(14.7,50.68) v1(14.95,62.33) v1(14.9,59.63) v1(15.1,6.18) v1(15.35,66.88) v1(15.3,50.68) v1(16.05,66.53) v1(16.2,16.18) v1(16.3,67.73) v1(16.4,12.18) v1(16.5,54.28) v1(16.5,48.08) v1(16.5,10.38) v1(16.6,48.83) v1(16.8,41.68) v1(16.8,40.78) v1(16.8,12.98) v1(16.75,11.38) v1(17.35,66.48) v1(17.5,41.68) v1(17.5,40.78) v1(17.5,39.98) v1(17.55,24.88) v1(17.6,21.18) v1(17.55,19.58) v1(17.9,56.83) v1(18,52.08) v1(18.15,44.53) v1(18.2,54.28) v1(18.55,50.28) v1(18.55,49.18) v1(18.65,48.13) v1(18.6,46.98) v1(18.6,46.28) v1(18.6,45.63) v1(18.7,51.68) v1(18.75,54.73) v1(19.1,55.38) v1(19.05,16.13) v1(19.45,63.48) v1(20.4,24.73) v1(20.75,21.18) v1(20.75,19.63) v1(20.8,12.08) v1(20.95,8.63) v1(20.95,7.43) v1(21,6.13) v1(21.15,65.28) v1(21.2,59.58) v1(21.35,15.28) v1(21.35,4.68) v1(21.4,3.28) v1(21.4,2.08) v1(22.2,66.53) v1(22.25,64.13) v1(22.2,58.48) v1(22.4,57.28) v1(22.45,29.23) v1(22.5,12.58) v1(22.55,20.53) v1(22.6,1.88) v1(22.8,62.33) v1(22.8,60.88) v1(22.75,4.93) v1(22.9,34.28) v1(23.2,65.58) v1(23.2,59.33) v1(23.5,15.33) v1(23.9,63.88) v1(24,62.58) v1(24,30.38) v1(24.25,14.48) v1(24.2,4.98) v1(24.35,58.23) v1(24.45,18.48) v1(24.54,61.45) v1(24.5,25.73) v1(24.5,1.88) v1(24.55,60.48) v1(24.65,31.63) v1(24.8,28.13) v1(24.9,65.98) v1(25,64.08) v1(25.3,15.68) v1(25.4,12.18) v1(25.6,67.58) v1(25.6,58.28) v1(25.75,61.45) v1(25.8,24.78) v1(25.8,20.48) v1(25.8,13.68) v1(26.4,62.63) v1(26.4,12.68) v1(26.6,65.33) v1(26.55,29.33) v1(26.6,14.48) v1(26.9,66.48) v1(26.85,46.98) v1(26.9,44.98) v1(26.9,44.48) v1(26.95,11.28) v1(27.25,67.38) v1(27.24,58.36) v1(27.4,47.38) v1(27.53,63.74) v1(27.5,62.68) v1(27.85,16.43) v1(27.9,5.13) v1(28.1,66.48) v1(28.1,61.78) v1(28.1,61.13) v1(28.45,63.58) v1(28.35,21.18) v1(28.5,3.58) v1(28.6,67.98) v1(28.6,67.03) v1(28.6,65.53) v1(28.55,41.88) v1(28.65,40.08) v1(28.72,64.07) v1(28.7,11.98) v1(29.3,5.18) v1(29.4,37.53) v1(29.52,53.22) v1(29.55,58.88) v1(29.6,52.38) v1(29.58,51.52) v1(29.6,50.68) v1(29.55,49.84) v1(29.8,33.88) v1(29.8,4.68) v1(30.2,10.58) v1(30.3,41.88) v1(30.45,16.43) v1(30.4,13.38) v1(30.5,39.33) v1(30.6,63.93) v1(30.6,63.23) v1(30.55,35.33) v1(30.7,62.33) v1(30.7,61.43) v1(30.7,60.53) v1(30.7,59.58) v1(30.75,58.73) v1(31,10.53) v1(31.05,37.53) v1(31.2,53.16) v1(31.3,52.38) v1(31.29,51.53) v1(31.3,50.68) v1(31.27,49.8) v1(31.3,33.73) v1(31.4,63.23) v1(31.4,62.33) v1(31.4,61.43) v1(31.4,60.53) v1(31.4,59.58) v1(31.4,58.68) v1(31.6,39.33) v1(31.6,24.78) v1(31.65,19.78) v1(32.05,41.83) v1(32.2,44.48) v1(32.2,34.78) v1(32.65,37.53) v1(32.7,44.48) v1(32.8,39.28) v1(32.8,10.53) v1(32.95,53.17) v1(32.9,36.78) v1(33,52.38) v1(32.97,51.5) v1(33,50.68) v1(32.97,49.78) v1(33.1,16.43) v1(33.25,33.63) v1(33.55,63.38) v1(33.55,61.73) v1(33.55,60.83) v1(33.55,59.28) v1(33.55,58.43) v1(33.55,57.43) v1(33.5,44.48) v1(33.65,29.38) v1(33.6,8.08) v1(33.7,13.28) v1(33.7,9.38) v1(33.9,40.03) v1(33.9,37.53) v1(34,62.73) v1(34.05,57.53) v1(34,44.48) v1(34.05,20.33) v1(34.25,61.34) v1(34.25,60.08) v1(34.25,59.28) v1(34.21,58.44) v1(34.3,10.58) v1(34.35,64.03) v1(34.65,30.63) v1(34.9,28.03) v1(34.9,24.88) v1(34.9,16.58) v1(35.15,21.73) v1(35.25,62.78) v1(35.25,4.83) v1(35.3,10.58) v1(35.55,61.38) v1(35.55,59.53) v1(35.6,17.73) v1(35.8,64.03) v1(36,44.88) v1(35.95,43.38) v1(36,41.88) v1(35.95,39.33) v1(35.95,37.53) v1(35.95,35.68) v1(35.95,33.98) v1(36,0.58) v1(36.1,19.13) v1(36.2,13.28) v1(36.4,67.98) v1(36.45,66.83) v1(36.45,65.63) v1(36.55,55.08) v1(36.65,4.93) v1(36.9,7.68) v1(36.95,4.08) v1(37.1,55.58) v1(37.1,32.08) v1(37.3,10.58) v1(37.6,16.28) v1(37.7,0.58) v1(37.75,53.18) v1(37.8,22.38) v1(37.9,43.48) v1(37.9,41.93) v1(37.9,39.38) v1(37.9,36.83) v1(37.9,34.18) v1(38.15,24.93) v1(38.1,2.68) v1(38.2,7.78) v1(38.25,1.48) v1(38.3,27.98) v1(38.4,17.08) v1(38.4,9.88) v1(38.45,52.58) v1(38.5,46.28) v1(38.55,15.38) v1(38.45,13.48) v1(38.5,8.78) v1(38.5,5.18) v1(38.65,67.78) v1(38.6,6.88) v1(38.7,56.28) v1(38.7,54.28) v1(38.8,50.68) v1(38.9,62.23) v1(38.9,45.88) v1(39.15,0.58) v1(39.2,57.78) v1(39.3,50.68) v1(39.3,37.43) v1(39.55,32.63) v1(39.7,47.78) v1(39.7,44.38) v1(39.7,41.93) v1(39.75,40.03) v1(39.75,38.58) v1(39.9,34.98) v1(39.85,23.13) v1(39.9,18.98) v1(40.05,63.48) v1(40.1,52.58) v1(40.25,6.08) v1(40.3,58.98) v1(40.3,49.18) v1(40.4,10.88) v1(40.45,7.83) v1(40.65,67.78) v1(40.6,67.73) v1(40.65,65.48) v1(41.3,46.18) v1(41.5,58.58) v1(41.55,35.78) v1(41.45,21.83) v1(41.45,6.08) v1(41.6,44.38) v1(41.65,41.88) v1(41.65,39.78) v1(41.6,37.88) v1(41.6,33.58) v1(41.65,31.03) v1(41.8,47.78) v1(41.9,57.38) v1(42,62.18) v1(42,58.08) v1(42.05,23.13) v1(42.2,11.68) v1(42.2,9.53) v1(42.3,52.58) v1(42.3,49.78) v1(42.4,5.43) v1(42.65,46.88) v1(42.6,0.88) v1(42.8,56.48) v1(42.85,15.53) v1(43.05,65.43) v1(43.15,38.38) v1(43.15,36.18) v1(43.15,33.78) v1(43.1,29.18) v1(43.15,1.98) v1(43.2,58.98) v1(43.2,44.53) v1(43.2,41.08) v1(43.2,31.38) v1(43.5,56.28) v1(43.65,67.78) v1(43.65,23.28) v1(43.7,45.88) v1(43.7,43.68) v1(43.8,53.28) v1(43.75,50.08) v1(43.8,49.18) v1(43.8,26.78) v1(43.85,48.23) v1(44,63.13) v1(44,55.78) v1(44,25.18) v1(44,9.58) v1(44.1,11.23) v1(44.4,54.18) v1(44.45,2.43) v1(44.7,57.88) v1(44.85,24.53) v1(45.4,43.53) v1(45.4,40.08) v1(45.35,37.58) v1(45.35,3.13) v1(45.5,56.08) v1(45.5,46.28) v1(45.5,42.58) v1(45.5,41.48) v1(45.45,34.78) v1(45.5,26.68) v1(45.55,13.28) v1(45.6,44.83) v1(45.65,22.08) v1(45.6,6.18) v1(45.75,65.18) v1(46,32.58) v1(46.15,10.63) v1(46.15,9.08) v1(46.3,22.08) v1(46.4,3.13) v1(46.5,55.08) v1(46.5,39.13) v1(46.55,18.83) v1(46.55,15.58) v1(46.6,67.83) v1(46.75,6.88) v1(46.95,53.68) v1(47.1,45.28) v1(47.1,14.58) v1(47.25,22.33) v1(47.3,9.13) v1(47.35,37.78) v1(47.5,40.23) v1(47.55,35.13) v1(47.45,31.08) v1(47.65,29.68) v1(47.75,3.13) v1(47.9,33.43) v1(48.2,45.03) v1(48.25,40.98) v1(48.3,28.68) v1(48.3,12.88) v1(48.4,26.68) v1(48.65,53.68) v1(48.65,10.13) v1(48.7,48.98) v1(48.8,50.48) v1(48.8,24.03) v1(48.85,57.48) v1(48.85,22.33) v1(49.05,7.83) v1(49.15,14.68) v1(49.15,3.13) v1(49.3,39.03) v1(49.4,40.48) v1(49.35,6.08) v1(49.45,46.03) v1(49.5,25.23) v1(49.6,37.68) v1(49.65,34.93) v1(50.25,58.78) v1(50.2,26.68) v1(50.25,22.68) v1(50.25,15.58) v1(50.4,33.23) v1(50.45,40.98) v1(50.55,8.93) v1(50.55,7.38) v1(50.65,54.83) v1(50.6,10.48) v1(50.6,3.13) v1(50.8,17.78) v1(50.75,13.88) v1(50.85,57.48) v1(50.85,51.43) v1(50.9,29.03) v1(50.85,16.43) v1(51.05,44.53) v1(51.2,40.28) v1(51.35,23.48) v1(51.45,56.23) v1(51.6,59.38) v1(51.6,43.13) v1(51.7,61.68) v1(51.8,38.58) v1(51.8,35.98) v1(51.8,32.88) v1(52.05,14.88) v1(52.1,43.98) v1(52.15,30.53) v1(52.15,3.13) v1(52.5,10.48) v1(52.55,8.68) v1(52.5,7.43) v1(52.6,18.03) v1(52.6,16.38) v1(52.8,53.38) v1(52.75,45.03) v1(52.8,43.38) v1(53.05,28.23) v1(53,23.48) v1(53.1,26.38) v1(53.4,36.93) v1(53.5,34.28) v1(53.45,31.88) v1(53.5,15.98) v1(53.45,14.08) v1(53.5,3.13) v1(53.8,19.33) v1(53.9,56.43) v1(53.9,22.53) v1(53.85,17.18) v1(53.9,7.58) v1(53.95,20.93) v1(54,10.48) v1(53.95,8.93) v1(54.1,5.68) v1(54.85,58.73) v1(54.95,24.88) v1(55.55,3.13) v1(56.65,43.33) v1(56.7,41.03) v1(56.9,45.98) v1(57,48.53) v1(57.15,24.88) v1(57.4,67.33) v1(57.35,64.33) v1(57.4,58.63) v1(57.4,56.28) v1(57.6,61.53) v1(58.2,41.78) v1(58.2,3.18) v1(58.35,25.53) v1(58.35,4.08) v1(58.75,61.23) v1(58.75,54.83) v1(58.75,52.28) v1(59.65,27.93) v1(59.7,19.53) v1(59.8,32.83) v1(59.8,31.23) v1(59.8,30.28) v1(59.75,22.03) v1(59.75,21.13) v1(59.75,18.58) v1(59.75,16.98) v1(59.75,16.03) v1(59.8,14.43) v1(59.8,9.23) v1(59.75,8.48) v1(59.75,6.78) v1(59.75,5.93) v1(59.9,45.98) v1(59.85,38.83) v1(59.85,37.88) v1(59.85,36.33) v1(59.9,35.33) v1(59.85,33.78) v1(59.85,13.53) v1(59.85,11.88) v1(59.85,10.98) v1(59.9,3.18) v1(60.1,28.68) v1(60.5,48.58) v1(60.7,41.08) v1(60.85,43.33) v1(61,56.28) v1(61.1,54.23) v1(61.35,24.83) v1(61.5,65.03) v1(61.9,61.33) v1(61.9,58.63) v1(62.65,24.83)
TL_32KI_C3: length 18
  TOP w0.2: J2.2 49.65,51.83 36.51,51.83 36.4,51.72 U1.31
TL_32KO_C2: length 13.4
  TOP w0.2: J4.2 45.55,51.43 36.68,51.43 36.47,51.22 U1.30
TL_ANT: length 2.5
  TOP w0.25: 32.48,56.03 U1.40
  TOP w0.5: C8.1 C9.2 32.48,56.03
TL_AS0_C5: length 44.6
  TOP w0.2: J9.6 J8.6 53.55,41.9 53.55,50.55 52.47,51.63 51.62,51.63 45.8,57.45 45.8,58.65 44.37,60.08 39,60.08 38.1,59.18 38.1,58.45 35.9,56.25 35.9,56.04 34.69,54.84 34.58,54.67 U1.36
TL_AS1_C6: length 37.7
  TOP w0.2: J9.9 J8.9 53.95,49.12 53.95,50.71 52.63,52.03 51.78,52.03 46.3,57.51 46.3,58.71 44.53,60.48 38.83,60.48 37.7,59.35 37.7,58.61 35.5,56.41 35.5,56.23 34.09,54.82 U1.37
TL_AS2_C7: length 36.9
  TOP w0.2: U1.38 33.48,55.34 33.62,55.48 34.18,55.48 35.1,56.39 35.1,56.58 37.3,58.78 37.3,59.51 37.77,59.98 38.67,60.88 39,60.88 44.7,60.88 46.8,58.78 46.8,57.58 51.95,52.43 52.8,52.43 55.42,49.81 J8.10 J9.10
TL_AUDIO_C1: length 31.4
  TOP w0.2: U1.29 C25.2 38.09,49.93 40.65,49.93 44.42,46.16 44.42,32.06 47,29.48 J22.2
TL_C0: length 28.1
  TOP w0.2: J20.2 42.4,46.08 38.95,49.53 37.85,49.53 37.4,49.98 36.9,49.98 36.66,50.22 U1.28
TL_CK_A4: length 50.6
  TOP w0.2: U1.6 24.84,51.72 24.23,51.11 24.23,37.75 19.98,33.5 14.76,33.5 9.6,28.35 9.6,22.08 8.79,21.27 4.51,21.27 3.56,20.32 J6.7
TL_CN_D6: length 44.6
  TOP w0.2: U1.48 24.55,54.82 21.83,52.1 21.83,38.75 18.99,35.91 13.76,35.91 10.04,32.18 8.4,32.18 7.9,31.68 4.77,31.68 3.56,30.48 J6.11
TL_D0: length 51.6
  TOP w0.2: U1.42 31.48,55.38 29.47,57.39 23.72,57.39 19.43,53.1 19.43,40.56 v1(18.65,39.78) ; v1(18.8,37.48) 18.02,36.7 13.43,36.7 11.31,34.58 9,34.58 8.7,34.88 8.7,36.18 8.17,36.71 4.71,36.71 3.56,35.56 J6.13
  BOTTOM w0.2: v1(18.65,39.78) 18.65,39.31 18.8,39.16 v1(18.8,37.48)
TL_D1: length 49.3
  TOP w0.2: J6.12 3.56,33.02 4.73,34.18 11.47,34.18 13.6,36.3 18.43,36.3 v1(19.6,37.48) ; U1.43 30.98,55.32 29.31,56.99 23.89,56.99 19.83,52.93 19.83,40.11 19.54,39.82 v1(19.54,39.78)
  BOTTOM w0.2: v1(19.6,37.48) 19.6,37.95 19.54,38.01 v1(19.54,39.78)
TL_D7: length 45.9
  TOP w0.2: J6.10 3.56,27.94 4.71,29.09 8.1,29.09 8.69,29.68 8.69,30.95 8.65,30.99 8.65,31.43 9,31.78 10.2,31.78 13.93,35.5 19.15,35.5 22.23,38.58 22.23,51.94 24.51,54.22 U1.1
TL_DI_A3: length 48.3
  TOP w0.2: U1.5 24.78,52.22 23.83,51.27 23.83,37.92 19.82,33.91 14.59,33.91 9.2,28.51 9.2,24.68 8.53,24.01 4.71,24.01 3.56,22.86 J6.8
TL_DM_A5: length 20
  TOP w0.2: v1(25.07,51.17) 25.12,51.22 U1.7 ; J27.2 12.39,55.53 17.99,55.53 19.06,56.6 v1(20.18,56.6)
  BOTTOM w0.2: v1(20.18,56.6) 22.08,56.6 24.6,54.08 24.6,51.64 v1(25.07,51.17)
TL_DMICCK_A1: length 70.2
  TOP w0.2: v1(12.48,20.46) 12.48,27.2 v1(11.42,28.26) ; U1.3 24.64,53.22 23.03,51.6 23.03,38.25 19.48,34.7 14.26,34.7 10.33,30.78 v1(9.8,30.78) ; v1(11.7,17.28) 11.7,16.81 11.33,16.44 11.32,16.44 11.09,16.22 11.09,10.47 13.23,8.33 16.98,8.33 17.7,7.61 17.7,4.08 J40.2
  BOTTOM w0.2: v1(12.48,20.46) 12.25,20.23 12.25,20.15 12.1,20 12.1,18.01 11.7,17.61 v1(11.7,17.28) ; v1(11.42,28.26) 11.09,28.59 11.09,29.49 v1(9.8,30.78)
TL_DMICDI_A0: length 65.6
  TOP w0.2: v1(10.95,27.71) 12.08,26.58 12.08,21.23 11.7,20.85 v1(11.7,20.38) ; v1(11.04,16.94) 10.69,16.59 10.69,10.31 13.82,7.18 J41.2 ; v1(9.2,31.18) 9.35,31.33 10.32,31.33 14.09,35.1 19.32,35.1 22.63,38.42 22.63,51.77 24.58,53.72 U1.2
  BOTTOM w0.2: v1(9.2,31.18) 9.2,30.48 10.6,29.08 10.6,28.06 v1(10.95,27.71) ; v1(11.04,16.94) 11.04,17.52 11.7,18.18 v1(11.7,20.38)
TL_DO_A2: length 46.2
  TOP w0.2: J6.9 3.56,25.4 4.8,26.63 8.35,26.63 8.8,27.08 8.8,28.68 14.43,34.3 19.65,34.3 23.43,38.08 23.43,51.44 24.71,52.72 U1.4
TL_DP_A6: length 27.1
  TOP w0.2: J28.2 9.05,56.39 13.83,56.39 14.29,55.93 17.82,55.93 19.37,57.48 v1(20.1,57.48) ; U1.8 26.06,50.72 26.06,50.67 v1(25.59,50.67)
  BOTTOM w0.2: v1(25.59,50.67) 25.54,50.62 24.84,50.62 24.2,51.26 24.2,53.88 22.03,56.05 19.92,56.05 19.59,56.38 19.59,56.97 v1(20.1,57.48)
TL_IO: length 64.5
  TOP w0.2: v1(13.5,58.08) 15.1,58.08 R12.2 ; J35.2 12.43,44.71 12.43,45.05 12.03,45.45 12.03,51.7 12.03,51.71 v1(12.03,52.44)
  TOP w0.5: J35.2 13.25,43.39 v1(13.25,40.48) ; U2.6 18.72,12.88 C22.1 19.8,13.58 18.3,15.08 v1(12.34,15.08) ; v1(13.2,37.28) 12.76,36.84 12.31,36.84 v1(10.6,35.13)
  BOTTOM w0.2: v1(13.5,58.08) 13.5,54.58 12.03,53.11 v1(12.03,52.44)
  BOTTOM w0.5: v1(10.6,35.13) 8.49,33.02 J7.4 5.57,31.04 5.57,22.31 10,17.88 10,16.78 11.7,15.08 v1(12.34,15.08) ; v1(13.25,40.48) 13.25,39.86 13.2,39.81 v1(13.2,37.28)
TL_KEY_B2: length 63.6
  TOP w0.2: SW3.3 SW3.1 ; SW3.1 25.6,32.78 25.6,47.68 26.64,48.72 U1.12 ; SW3.1 24.55,29.33 24.35,29.33 SW2.1 SW2.3 15.9,25 14.88,23.98 14.88,20.25 14.36,19.74 11.37,19.74 9.09,17.47 9.09,14.25 J13.4 J6.4
TL_KEY_B3: length 77.8
  TOP w0.2: U1.13 26.74,48.12 26.1,47.48 26.1,34.28 27.5,32.88 33.6,32.88 35.73,30.75 35.73,24.05 34.45,22.78 SW5.3 SW5.1 SW4.3 SW4.1 16,20.44 14.91,19.34 11.53,19.34 9.49,17.3 9.49,12.11 J13.3 J6.3
TL_KEY_B4: length 95.8
  TOP w0.2: J6.2 J13.2 9.89,9.97 9.89,17.14 10.98,18.23 14.9,18.23 14.96,18.28 SW4.2 SW4.4 23.32,17.16 33.57,17.16 34.37,17.96 34.37,18.96 37,21.59 37,30.13 34.7,32.43 34.7,45.98 32.98,47.7 U1.22 ; SW2.2 SW2.4 14.6,30.28 14.6,24.27 14.26,23.93 v1(14.26,20.42)
  BOTTOM w0.2: SW4.2 14.88,19.41 14.88,19.8 v1(14.26,20.42)
TL_KEY_B5: length 87.2
  TOP w0.2: v1(36.4,26.48) 36.4,21.58 SW5.4 SW5.2 ; U1.23 33.48,47.77 35.23,46.01 35.23,32.78 37.6,30.41 v1(37.6,26.48) ; SW3.2 SW3.4 ; J6.1 J13.1 8.69,6.23 8.69,8.17 10.29,9.77 10.29,16.97 11.15,17.83 14.86,17.83 15.53,17.16 22.76,17.16 23.31,16.6 v1(25.4,16.6)
  BOTTOM w0.2: v1(37.6,26.48) v1(36.4,26.48) 35.8,27.08 SW3.4 ; SW5.2 25.73,17.11 25.73,16.94 v1(25.4,16.6)
TL_P0_D5: length 39.5
  TOP w0.2: U1.47 28.98,55.05 28.64,55.39 24.55,55.39 21.43,52.27 21.43,39.19 20.27,38.03 11.25,38.03 10.08,39.2 J38.7
TL_P1N_D3: length 45.6
  TOP w0.2: U1.45 29.98,55.19 28.98,56.19 24.22,56.19 20.63,52.6 20.63,39.53 19.93,38.83 11.58,38.83 10.88,39.53 10.88,42.48 11.63,43.23 11.63,44.72 11.23,45.12 11.23,48.01 J38.3
TL_P2_C4: length 47.8
  TOP w0.2: U1.35 34.94,53.72 35.2,53.98 35.2,54.78 36.3,55.88 36.3,56.08 38.5,58.28 38.5,58.98 39.2,59.68 44.2,59.68 45.4,58.48 45.4,57.25 47.5,55.15 v1(47.5,54.68) ; J9.5 J8.5
  BOTTOM w0.2: J8.5 53.6,39.31 53.6,51.08 50,54.68 v1(47.5,54.68)
TL_P2N_D4: length 42.8
  TOP w0.2: J38.5 10.83,45.87 10.83,44.95 11.23,44.55 11.23,43.4 10.48,42.65 10.48,39.36 11.42,38.43 20.1,38.43 21.03,39.36 21.03,52.43 24.39,55.79 28.81,55.79 29.48,55.12 U1.46
TL_P3_D2: length 48.3
  TOP w0.2: J38.1 11.63,50.15 11.63,45.28 12.03,44.88 12.03,43.07 11.28,42.32 11.28,39.7 11.75,39.23 19.77,39.23 20.23,39.69 20.23,52.76 24.06,56.59 29.14,56.59 30.48,55.25 U1.44
TL_RST: length 184.9
  TOP w0.2: v1(59.75,52.03) 59.75,55.93 58.2,57.48 57.4,57.48 56.8,58.08 56.8,64.53 SW1.3 SW1.1 43.55,61.28 38.5,61.28 36.9,59.68 36.9,59.33 C15.2 34.7,57.13 34.7,56.63 33.95,55.88 33.4,55.88 32.98,55.46 U1.39
  BOTTOM w0.2: v1(59.75,52.03) 59.05,51.33 59.05,5.83 56.9,3.68 43.15,3.68 41.45,5.38 39.7,5.38 35.45,1.13 15.6,1.13 15.1,1.63 15.1,3.58 13.6,5.08 11.3,5.08 10,3.78 5.8,3.78 4,5.58 4,32.01 J7.3
TL_SDMN1_B7: length 53.8
  TOP w0.2: J17.1 24.8,11.55 24.8,13.53 26.7,15.43 35.92,15.43 39,18.51 39,23.91 39.5,24.41 39.5,31.27 37.12,33.65 37.12,45.37 34.58,47.91 U1.25
TL_SDMP1_B6: length 53.1
  TOP w0.2: U1.24 33.98,47.95 36.73,45.2 36.73,33.48 39.1,31.1 39.1,24.58 38.6,24.08 38.6,18.68 35.75,15.83 26.53,15.83 24.4,13.7 24.4,11.05 J16.1
TL_SWS_A7: length 53.6
  TOP w0.2: v1(1.6,58.78) 1.6,64.38 2.82,65.6 11.93,65.6 12.11,65.78 19.6,65.78 22.1,63.28 22.1,59.39 23.1,58.39 v1(23.1,57.78) ; U1.9 26.11,50.22 v1(25.14,49.24)
  BOTTOM w0.2: J18.5 1.61,58.78 v1(1.6,58.78) ; v1(25.14,49.24) 26.26,49.24 26.9,49.88 26.9,51.48 25.9,52.48 25.9,54.98 v1(23.1,57.78)
  BOTTOM w0.5: J18.8 J18.5
TL_URX_B0: length 50.6
  TOP w0.2: J6.6 J13.6 8.27,17.78 10.15,19.66 10.15,26.91 10,27.06 10,28.18 14.92,33.1 20.15,33.1 24.63,37.59 24.63,46.14 24.78,46.29 24.78,48.11 26.39,49.72 U1.10
TL_UTX_B1: length 52.2
  TOP w0.2: J6.5 J13.5 8.69,16.39 8.69,17.63 10.55,19.49 10.55,27.08 10.4,27.23 10.4,28.02 15.09,32.7 20.31,32.7 25.03,37.42 25.03,45.97 25.18,46.12 25.18,47.94 26.46,49.22 U1.11
TL_VBUS: length 27.6
  TOP w0.25: U1.26 35.16,49.22 35.4,48.98 35.4,48.18
  TOP w0.5: 33.57,38.41 v1(34.07,38.41) v1(34.07,38.91) 33.57,38.41 ; 33.57,38.41 J42.2 ; v1(38.8,38.41) v1(38.8,38.91) 38.8,44.58 37.05,46.33 C27.1 36.85,46.73 35.4,48.18
  BOTTOM w0.5: 38.3,38.41 v1(38.8,38.91) v1(38.8,38.41) 38.3,38.41 ; 38.3,38.41 34.57,38.41 ; 34.57,38.41 v1(34.07,38.41) v1(34.07,38.91) 34.57,38.41
TL_VDD: length 89.7
  TOP w0.25: U1.27 35.66,49.72 C13.1 ; C16.1 28.52,45.9 28.52,45.97 29.98,47.42 U1.16
  TOP w0.5: v1(27.7,40.98) v1(28.2,40.98) 33.5,40.98 ; 33.5,40.98 v1(34,41.48) v1(34,40.98) 33.5,40.98 ; v1(18.4,41.28) v1(18.4,42.08) 18.4,42.98 C29.1 18.34,43.64 J29.2 16.04,43.64 J35.1 ; C13.1 36.1,48.66 36.88,47.88 38.2,47.88 40.6,45.48 v1(40.6,41.48) v1(40.6,40.98) ; C16.1 28.1,44.08 27.7,43.68 v1(27.7,42.58) v1(27.7,42.08)
  BOTTOM w0.5: 40.1,40.98 v1(40.6,40.98) v1(40.6,41.48) 40.1,40.98 ; 40.1,40.98 34.5,40.98 ; v1(28.2,40.98) v1(27.7,40.98) 23,40.98 22.7,41.28 v1(18.4,41.28) ; 34.5,40.98 v1(34,41.48) v1(34,40.98) 34.5,40.98 ; 27.2,42.08 v1(27.7,42.08) v1(27.7,42.58) 27.2,42.08 ; 27.2,42.08 v1(18.4,42.08) ; J35.1 11.8,44.48 11.8,43.96 10.32,42.48 6.15,42.48 3.56,45.07 J18.6 J18.7
TL_XC1: length 8.6
  TOP w0.2: C3.2 39.99,57.57 Y1.3 39.99,56.37 39.1,55.48 38,55.48 36.8,54.28 36.26,54.28 36.01,54.03 36.01,54.03 35.2,53.22 U1.34
TL_XC2: length 10.8
  TOP w0.2: U1.33 35.27,52.72 36.18,53.63 36.43,53.88 36.97,53.88 38.17,55.08 40.78,55.08 41.92,53.94 Y1.1 42.81,54.78 C4.2
USB_5V: length 94.5
  TOP w0.2: U4.1 15.35,52.53 14.9,52.98 13.78,52.98 13.45,52.64 U4.3
  TOP w0.5: U4.1 16.22,51.8 C30.1 17.82,53.4 18.96,53.4 21.58,56.02 21.58,58 20.6,58.98 18.3,58.98 17.33,59.95 J26.1 17.33,62.35 16.3,63.38 15.8,63.38 14.45,64.73 12.65,64.73 12,64.08 8.27,64.08 J18.4 0.6,56.41 0.6,45.04 J7.2
  BOTTOM w0.5: 11.3,34.84 20.66,34.84 21.69,35.87 J42.1 ; 11.3,34.84 11.3,35.42 10.89,35.83 9.81,35.83 J7.2 ; 11.3,34.84 8.4,31.94 8.4,31.34 J7.5 ; J18.9 J18.4
N19472288: length 2.4
  TOP w0.2: J38.4 6.82,49.88 R4.1
N19472291: length 3.5
  TOP w0.2: J38.8 5.81,45.81 5.81,46.27 R6.1
N19472372: length 10.4
  TOP w0.2: L4.1 31.6,8.38 31.2,7.98 23.87,7.98 J16.2
N19472375: length 10.6
  TOP w0.2: L5.1 35.9,8.08 35.1,7.28 28.8,7.28 28.33,6.81 J17.2
N19472414: length 16
  TOP w0.2: J39.2 24.9,4.58 27.25,4.58 27.55,4.28 27.55,3.18 28.15,2.58 30.6,2.58 C20.2 C21.1 32.2,3.68 33.51,4.99 33.51,5.87 33.23,6.16 L4.2
N19472431: length 13.9
  TOP w0.2: L5.2 34.27,6.16 34,5.88 34,4.88 33.2,4.08 C21.2 ; J39.1 27.44,2.18 30.77,2.18 31.25,2.66 32.68,2.66 C21.2 ; C21.2 C23.1
N19472505: length 2.2
  TOP w0.2: J38.2 6.57,51.7 6.36,51.48 R3.1
N19497696: length 2.8
  TOP w0.2: R5.1 5.81,47.87 6.28,47.87 J38.6
N19519268: length 6.5
  TOP w0.2: J2.1 49.9,45.44 R1.2 49.9,43.34 Y2.2 50.67,42.57 50.67,42.51 C11.2
N19519271: length 6.6
  TOP w0.2: J4.1 48.9,45.54 R1.1 48.9,43.34 Y2.1 48.13,42.57 48.09,42.57 C10.2
N19526123: length 9.7
  TOP w0.2: R11.2 R12.1 14.8,58.58 14.45,58.93 9.05,58.93 J28.1
N19526133: length 2.8
  TOP w0.2: J26.3 15.73,59.71 16.25,59.19 16.42,59.19 16.6,59.01 R11.1
N19526168: length 2.8
  TOP w0.2: J26.2 16.53,59.65 R10.1
N19527038: length 6
  TOP w0.2: J27.1 12.39,57.49 14.29,57.49 14.75,57.03 17.05,57.03 R10.2
N19581488: length 5.9
  TOP w0.2: J20.1 40.5,23.08 R7.1
N19581502: length 3.7
  TOP w0.2: R7.2 41.5,18.98 C26.1 42.36,17.52 42.46,17.52 U3.4
N19581635: length 1
  TOP w0.2: R8.2 C24.1
N19581732: length 18.1
  TOP w0.2: J37.1 51.64,15.72 49.7,13.78 47.2,13.78 45.1,11.68 45.1,8.83 43.95,7.68 J23.2
N19602515: length 4.2
  TOP w0.2: J36.2 J37.2 48.4,21.08 C24.2
N19603583: length 7.7
  TOP w0.2: J22.1 47,23.78 46.6,23.38 44.93,23.38 44.15,22.6 42.72,22.6 42.2,22.08 R8.1
N19606656: length 9.4
  TOP w0.2: J40.1 20.19,4.03 20.19,8.69 19.8,9.08 R2.2 19.29,9.98 19.14,10.13 U2.4
N19606659: length 6.2
  TOP w0.2: U2.5 17.2,10.81 17.2,9.38 18,8.58 18.71,8.58 19.04,8.25 J41.1
N19611817: length 5.9
  TOP w0.2: J9.4 J8.4
N19611824: length 5.9
  TOP w0.2: J9.3 J8.3
N19611831: length 5.9
  TOP w0.2: J9.2 J8.2
N19611838: length 5.9
  TOP w0.2: J9.1 J8.1
N19611845: length 5.9
  TOP w0.2: J9.8 J8.8
N19611852: length 5.8
  TOP w0.2: J12.8 J11.8
N19611859: length 5.8
  TOP w0.2: J12.6 J11.6
N19611866: length 5.8
  TOP w0.2: J12.7 J11.7
N19611873: length 5.8
  TOP w0.2: J12.5 J11.5
N19611880: length 5.8
  TOP w0.2: J12.4 J11.4
N19611887: length 5.8
  TOP w0.2: J12.3 J11.3
N19611894: length 5.8
  TOP w0.2: J12.2 J11.2
N19611901: length 5.8
  TOP w0.2: J12.1 J11.1
N19648539: length 2.3
  TOP w0.2: C34.1 35.8,52.53 35.49,52.22 U1.32
N19648573: length 2.4
  TOP w0.25: U1.15 29.48,47.56 28.82,46.9 28.52,46.9 C14.2
N19648583: length 5.9
  TOP w0.25: U1.18 30.98,46.5 31.4,46.08 31.4,43.88 31.15,43.63 L3.1
N19648603: length 2.8
  TOP w0.25: 30.3,46.98 30.48,47.16 U1.17
  TOP w0.3: 30.3,46.98 30.05,46.73 30.05,45.5
N19648651: length 2.8
  TOP w0.2: U1.21 32.48,47.4 33,46.88 33.2,46.88 33.8,46.28 C19.1
N19650305: length 1.8
  TOP w0.5: L2.1 C6.2 C8.2
N19650315: length 1.7
  TOP w0.5: L2.2 C7.2 32.48,62.91 L6.1
N19656188: length 2.5
  TOP w0.5: L6.2 32.5,66.41 J1.1
N194723011: length 1.3
  TOP w0.2: D4.A R6.2
N194723090: length 1.3
  TOP w0.2: R3.2 D1.A
N194723171: length 1.3
  TOP w0.2: R4.2 D2.A
N194723250: length 1.3
  TOP w0.2: D3.A R5.2
N195815302: length 4.8
  TOP w0.2: U3.1 45.4,17.88 J36.1

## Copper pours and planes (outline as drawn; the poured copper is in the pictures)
GND on TOP: 10.2,0.3 7.66,2.84 1,2.84 0.51,3.05 0.3,3.54 0.3,65.53 1.1,67.48 3.05,68.28 30.8,68.28 30.8,64.48 31.65,63.63 31.65,56.38 33.3,56.38 33.3,63.58 34.5,64.78 34.5,68.28 60.29,68.28 62.24,67.48 63.04,65.53 63.04,4.19 61.69,2.84 45.26,2.84 42.72,0.3 ; 37 cut-outs
GND on BOTTOM: 10.2,0.3 7.66,2.84 1,2.84 0.51,3.05 0.3,3.54 0.3,65.53 1.1,67.48 3.05,68.28 60.29,68.28 62.24,67.48 63.04,65.53 63.04,4.19 61.69,2.84 45.26,2.84 42.72,0.3 ; 26 cut-outs

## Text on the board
User.Comments: RESET | IOREF | 3V3 | 5V | TX | RX | # | SCL | AREF | GND | 13 | 12 | 11 | 10 | 9 | 8 | 7 | 6 | 5 | 4 | 3 | 2 | 1 | 0 | SDA | A0 | A5 | VIN | A2 | A1 | A4 | A3 | [#=PWM] | www.arduino.cc | UNO_Rev3.01 | POWER | ANALOG IN | L | ON | DIGITAL | R10 | R9 | ESD1 | D1 | X1 | E1 | E2 | C3 | C4 | C5 | Cp1 | U2 | ZU4 | C12 | C2 | U1 | R2 | R1 | R3 | R8 | U5' | U5 | C8 | C10 | D2 | F1 | C1 | T1 | R6 | U3 | R14 | R15 | ICSP | R13 | Y2 | R12 | R7 | C11 | C9 | R4 | RESET-EN | R11 | C6 | L1 | X2 | C7 | Y1 | IOL | IOH | GROUND | Xduino
Ref Des/Silkscreen Top: PD0 | PD1 | PD6 | PD7 | PA2 | PA3 | PA4 | PB0 | PB1 | PB2 | PB3 | PB4 | PB5 | 5V | NC | RST | 3V3OUT | GND | PA1/DCK | PA0/DDI | B_D2 | G_D3 | W_D4 | R_D5 | AudioOut | PC7 | PC6 | PC5 | PC4 | SWS | 3V3 | DP/A6 | DM/A5 | 3V3CHIP | 3V3LDO | PB6/SP1 | PB7/SN1 | PC0/BIAS | PC1/Audio | C2/32KO | C3/32KI | 2019-10-24 | C1T197A30_V1.1 | TLSR8278DK48
COMPVAL_TYPE_TOP: 2019.11.18 | Reference | C9 | C8 | C6 | L2 | C7 | L6 | 220pF | 2.4nH | 1.5pF | 1.5nH | Value | HZF | 2pF | nc | UPDATA BOM | IC TLSR8278F1KET48 | Manufter | ZHU1933    EP7167.1 | Murata | Note
User.7: FIGURE | SIZE | 0.3 | 0.5 | 0.9 | 1.0 | DRILL CHART: TOP to BOTTOM | ALL UNITS ARE IN MILLIMETERS | PLATED | NON-PLATED | QTY | 735 | 2 | 109 | 20
